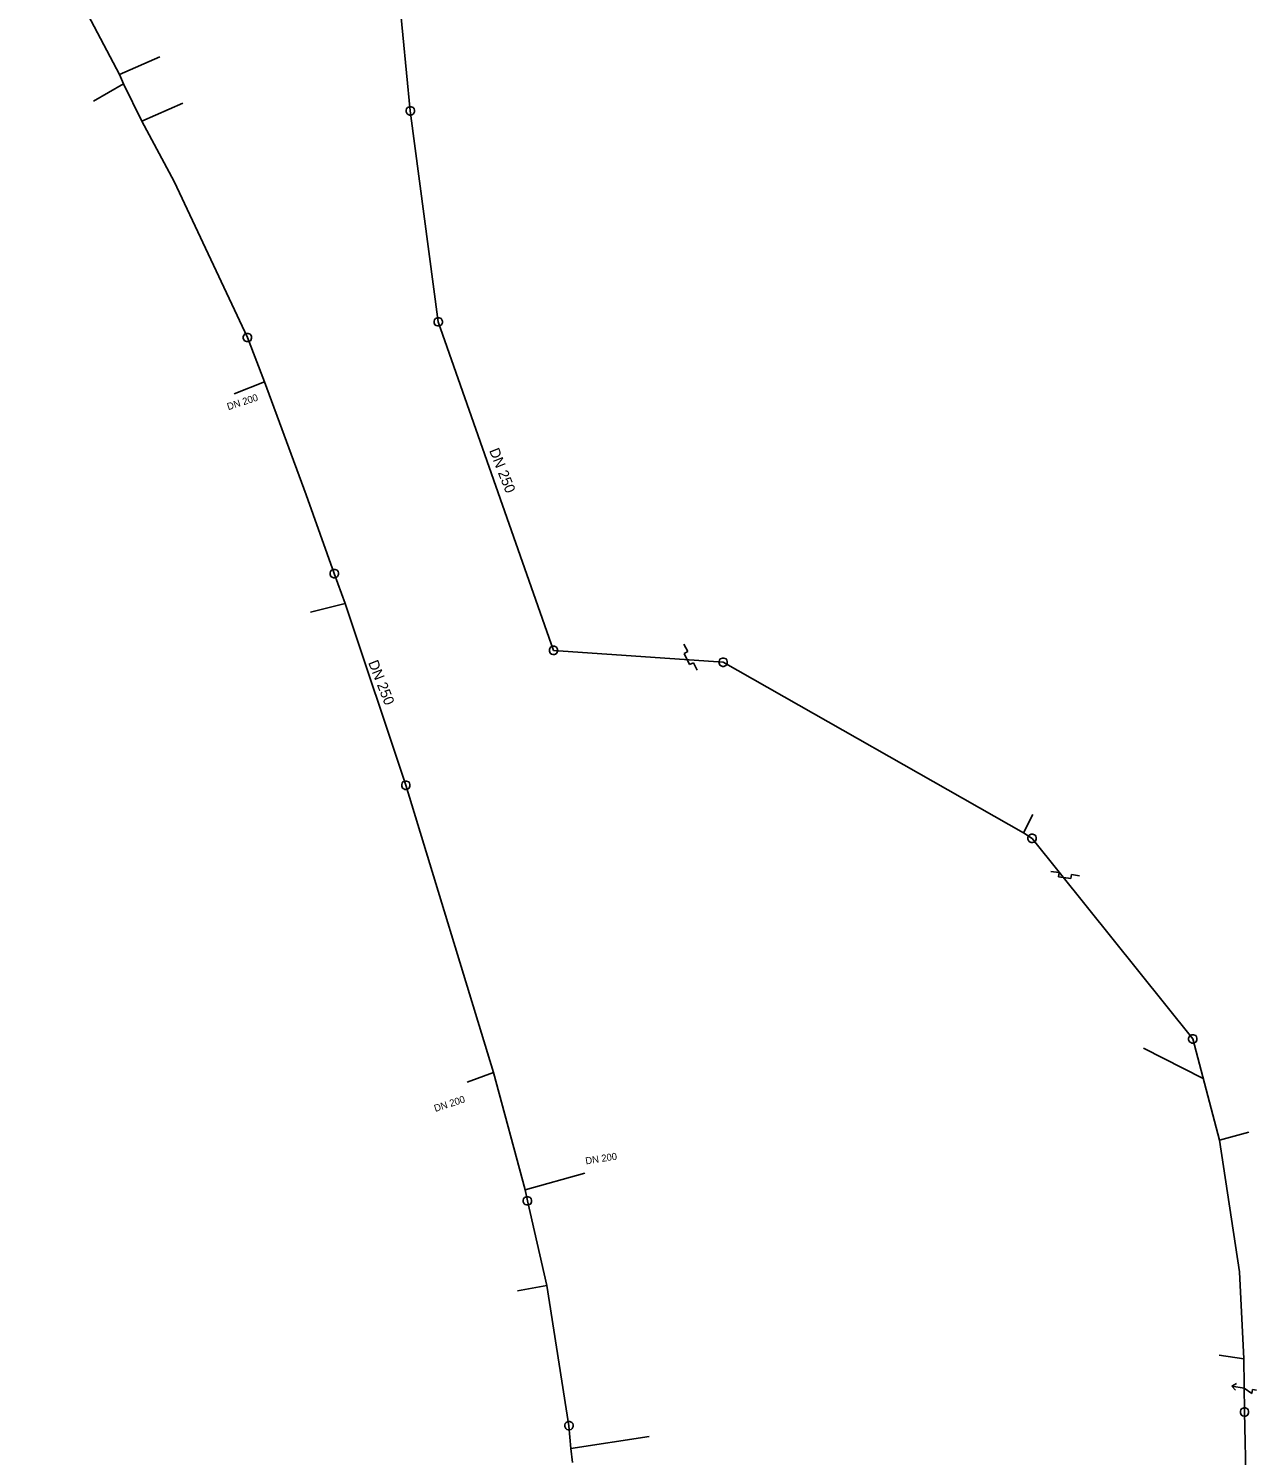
# Model space of a CAD drawing. Extents: x -717256 to -716843, y -1145423 to -1142840.
# Drawn here: x -717040.3 to -716891.8, y -1144735 to -1144562.5 of the extents above; entities that cross this region are included whole.
import ezdxf

# ---------------------------------------------------------------- set-up
doc = ezdxf.new("R2010")
doc.units = 0
for name, color, linetype in [('Vrstva 30', 7, 'Continuous'), ('Vrstva 31', 7, 'Continuous'), ('Vrstva 9', 7, 'Continuous')]:
    doc.layers.add(name, color=color, linetype=linetype)

msp = doc.modelspace()

# ---------------------------------------------------------------- linework, layer by layer
at = {"layer": 'Vrstva 30'}
for p, q in [((-716998.155, -1144530.526), (-716994.12, -1144572.47)), ((-717029.258, -1144568.056), (-717040.274, -1144547.245)), ((-717028.79, -1144569.2), (-717029.258, -1144568.056)), ((-717026.579, -1144573.721), (-717028.79, -1144569.2)), ((-716994.62, -1144572.37), (-716994.57, -1144572.22)), ((-716994.62, -1144572.57), (-716994.62, -1144572.37)), ((-716994.52, -1144572.82), (-716994.62, -1144572.57)), ((-716994.57, -1144572.22), (-716994.47, -1144572.07)), ((-716994.37, -1144572.92), (-716994.52, -1144572.82)), ((-716994.47, -1144572.07), (-716994.22, -1144571.97)), ((-716994.22, -1144572.97), (-716994.37, -1144572.92)), ((-716994.22, -1144571.97), (-716994.02, -1144571.97)), ((-716994.02, -1144572.97), (-716994.22, -1144572.97)), ((-716990.742, -1144597.967), (-716994.12, -1144572.47)), ((-716994.02, -1144571.97), (-716993.77, -1144572.07)), ((-716993.87, -1144572.92), (-716994.02, -1144572.97)), ((-716993.72, -1144572.82), (-716993.87, -1144572.92)), ((-716993.77, -1144572.07), (-716993.67, -1144572.22)), ((-716993.62, -1144572.57), (-716993.72, -1144572.82)), ((-716993.67, -1144572.22), (-716993.62, -1144572.37)), ((-716993.62, -1144572.37), (-716993.62, -1144572.57)), ((-717022.661, -1144581.009), (-717026.579, -1144573.721)), ((-717013.813, -1144599.855), (-717022.661, -1144581.009)), ((-716991.092, -1144597.567), (-716990.842, -1144597.467)), ((-716990.842, -1144597.467), (-716990.642, -1144597.467)), ((-716990.642, -1144597.467), (-716990.392, -1144597.567)), ((-716991.242, -1144597.867), (-716991.192, -1144597.717)), ((-716991.242, -1144598.067), (-716991.242, -1144597.867)), ((-716991.142, -1144598.317), (-716991.242, -1144598.067)), ((-716991.192, -1144597.717), (-716991.092, -1144597.567)), ((-716990.992, -1144598.417), (-716991.142, -1144598.317)), ((-716990.842, -1144598.467), (-716990.992, -1144598.417)), ((-716990.642, -1144598.467), (-716990.842, -1144598.467)), ((-716976.809, -1144637.685), (-716990.742, -1144597.967)), ((-716990.492, -1144598.417), (-716990.642, -1144598.467)), ((-716990.342, -1144598.317), (-716990.492, -1144598.417)), ((-716990.392, -1144597.567), (-716990.292, -1144597.717)), ((-716990.242, -1144598.067), (-716990.342, -1144598.317)), ((-716990.292, -1144597.717), (-716990.242, -1144597.867)), ((-716990.242, -1144597.867), (-716990.242, -1144598.067)), ((-717014.313, -1144599.755), (-717014.263, -1144599.605)), ((-717014.313, -1144599.955), (-717014.313, -1144599.755)), ((-717014.213, -1144600.205), (-717014.313, -1144599.955)), ((-717014.263, -1144599.605), (-717014.163, -1144599.455)), ((-717014.063, -1144600.305), (-717014.213, -1144600.205)), ((-717014.163, -1144599.455), (-717013.913, -1144599.355)), ((-717013.913, -1144600.355), (-717014.063, -1144600.305)), ((-717013.913, -1144599.355), (-717013.713, -1144599.355)), ((-717013.713, -1144600.355), (-717013.913, -1144600.355)), ((-717011.758, -1144605.221), (-717013.813, -1144599.855)), ((-717013.713, -1144599.355), (-717013.463, -1144599.455)), ((-717013.563, -1144600.305), (-717013.713, -1144600.355)), ((-717013.413, -1144600.205), (-717013.563, -1144600.305)), ((-717013.463, -1144599.455), (-717013.363, -1144599.605)), ((-717013.313, -1144599.955), (-717013.413, -1144600.205)), ((-717013.363, -1144599.605), (-717013.313, -1144599.755)), ((-717013.313, -1144599.755), (-717013.313, -1144599.955)), ((-717006.718, -1144618.872), (-717011.758, -1144605.221)), ((-717003.312, -1144628.399), (-717006.718, -1144618.872)), ((-717003.812, -1144628.299), (-717003.762, -1144628.149)), ((-717003.812, -1144628.499), (-717003.812, -1144628.299)), ((-717003.712, -1144628.749), (-717003.812, -1144628.499)), ((-717003.762, -1144628.149), (-717003.662, -1144627.999)), ((-717003.662, -1144627.999), (-717003.412, -1144627.899)), ((-717003.412, -1144627.899), (-717003.212, -1144627.899)), ((-717002.014, -1144631.998), (-717003.312, -1144628.399)), ((-717003.212, -1144627.899), (-717002.962, -1144627.999)), ((-717002.962, -1144627.999), (-717002.862, -1144628.149)), ((-717002.812, -1144628.499), (-717002.912, -1144628.749)), ((-717002.862, -1144628.149), (-717002.812, -1144628.299)), ((-717002.812, -1144628.299), (-717002.812, -1144628.499)), ((-717003.562, -1144628.849), (-717003.712, -1144628.749)), ((-717003.412, -1144628.899), (-717003.562, -1144628.849)), ((-717003.212, -1144628.899), (-717003.412, -1144628.899)), ((-717003.062, -1144628.849), (-717003.212, -1144628.899)), ((-717002.912, -1144628.749), (-717003.062, -1144628.849)), ((-716994.665, -1144653.982), (-717002.014, -1144631.998)), ((-716977.309, -1144637.585), (-716977.259, -1144637.435)), ((-716977.309, -1144637.785), (-716977.309, -1144637.585)), ((-716977.209, -1144638.035), (-716977.309, -1144637.785)), ((-716977.259, -1144637.435), (-716977.159, -1144637.285)), ((-716977.059, -1144638.135), (-716977.209, -1144638.035)), ((-716977.159, -1144637.285), (-716976.909, -1144637.185)), ((-716976.909, -1144638.185), (-716977.059, -1144638.135)), ((-716976.909, -1144637.185), (-716976.709, -1144637.185)), ((-716976.709, -1144638.185), (-716976.909, -1144638.185)), ((-716976.809, -1144637.685), (-716956.299, -1144639.117)), ((-716976.709, -1144637.185), (-716976.459, -1144637.285)), ((-716976.559, -1144638.135), (-716976.709, -1144638.185)), ((-716976.409, -1144638.035), (-716976.559, -1144638.135)), ((-716976.459, -1144637.285), (-716976.359, -1144637.435)), ((-716976.309, -1144637.785), (-716976.409, -1144638.035)), ((-716976.359, -1144637.435), (-716976.309, -1144637.585)), ((-716976.309, -1144637.585), (-716976.309, -1144637.785)), ((-716956.799, -1144639.017), (-716956.749, -1144638.867)), ((-716956.749, -1144638.867), (-716956.649, -1144638.717)), ((-716956.649, -1144638.717), (-716956.399, -1144638.617)), ((-716956.399, -1144638.617), (-716956.199, -1144638.617)), ((-716956.199, -1144638.617), (-716955.949, -1144638.717)), ((-716955.949, -1144638.717), (-716955.849, -1144638.867)), ((-716955.849, -1144638.867), (-716955.799, -1144639.017)), ((-716956.799, -1144639.217), (-716956.799, -1144639.017)), ((-716956.699, -1144639.467), (-716956.799, -1144639.217)), ((-716956.549, -1144639.567), (-716956.699, -1144639.467)), ((-716956.399, -1144639.617), (-716956.549, -1144639.567)), ((-716956.199, -1144639.617), (-716956.399, -1144639.617)), ((-716920.002, -1144659.717), (-716956.299, -1144639.117)), ((-716956.049, -1144639.567), (-716956.199, -1144639.617)), ((-716955.899, -1144639.467), (-716956.049, -1144639.567)), ((-716955.799, -1144639.217), (-716955.899, -1144639.467)), ((-716955.799, -1144639.017), (-716955.799, -1144639.217)), ((-716995.165, -1144653.882), (-716995.115, -1144653.732)), ((-716995.165, -1144654.082), (-716995.165, -1144653.882)), ((-716995.065, -1144654.332), (-716995.165, -1144654.082)), ((-716995.115, -1144653.732), (-716995.015, -1144653.582)), ((-716994.915, -1144654.432), (-716995.065, -1144654.332)), ((-716995.015, -1144653.582), (-716994.765, -1144653.482)), ((-716994.765, -1144653.482), (-716994.565, -1144653.482)), ((-716984.065, -1144688.705), (-716994.665, -1144653.982)), ((-716994.565, -1144653.482), (-716994.315, -1144653.582)), ((-716994.265, -1144654.332), (-716994.415, -1144654.432)), ((-716994.315, -1144653.582), (-716994.215, -1144653.732)), ((-716994.165, -1144654.082), (-716994.265, -1144654.332)), ((-716994.215, -1144653.732), (-716994.165, -1144653.882)), ((-716994.165, -1144653.882), (-716994.165, -1144654.082)), ((-716994.765, -1144654.482), (-716994.915, -1144654.432)), ((-716994.565, -1144654.482), (-716994.765, -1144654.482)), ((-716994.415, -1144654.432), (-716994.565, -1144654.482)), ((-716918.947, -1144660.401), (-716920.002, -1144659.717)), ((-716919.447, -1144660.301), (-716919.397, -1144660.151)), ((-716919.447, -1144660.501), (-716919.447, -1144660.301)), ((-716919.347, -1144660.751), (-716919.447, -1144660.501)), ((-716919.397, -1144660.151), (-716919.297, -1144660.001)), ((-716919.197, -1144660.851), (-716919.347, -1144660.751)), ((-716919.297, -1144660.001), (-716919.047, -1144659.901)), ((-716919.047, -1144660.901), (-716919.197, -1144660.851)), ((-716919.047, -1144659.901), (-716918.847, -1144659.901)), ((-716918.847, -1144660.901), (-716919.047, -1144660.901)), ((-716918.947, -1144660.401), (-716899.524, -1144684.642)), ((-716918.847, -1144659.901), (-716918.597, -1144660.001)), ((-716918.697, -1144660.851), (-716918.847, -1144660.901)), ((-716918.547, -1144660.751), (-716918.697, -1144660.851)), ((-716918.597, -1144660.001), (-716918.497, -1144660.151)), ((-716918.447, -1144660.501), (-716918.547, -1144660.751)), ((-716918.497, -1144660.151), (-716918.447, -1144660.301)), ((-716918.447, -1144660.301), (-716918.447, -1144660.501)), ((-716900.024, -1144684.542), (-716899.974, -1144684.392)), ((-716900.024, -1144684.742), (-716900.024, -1144684.542)), ((-716899.924, -1144684.992), (-716900.024, -1144684.742)), ((-716899.974, -1144684.392), (-716899.874, -1144684.242)), ((-716899.774, -1144685.092), (-716899.924, -1144684.992)), ((-716899.874, -1144684.242), (-716899.624, -1144684.142)), ((-716899.624, -1144685.142), (-716899.774, -1144685.092)), ((-716899.624, -1144684.142), (-716899.424, -1144684.142)), ((-716899.424, -1144685.142), (-716899.624, -1144685.142)), ((-716899.524, -1144684.642), (-716896.302, -1144696.881)), ((-716899.424, -1144684.142), (-716899.174, -1144684.242)), ((-716899.274, -1144685.092), (-716899.424, -1144685.142)), ((-716899.124, -1144684.992), (-716899.274, -1144685.092)), ((-716899.174, -1144684.242), (-716899.074, -1144684.392)), ((-716899.024, -1144684.742), (-716899.124, -1144684.992)), ((-716899.074, -1144684.392), (-716899.024, -1144684.542)), ((-716899.024, -1144684.542), (-716899.024, -1144684.742)), ((-716980.224, -1144702.883), (-716984.065, -1144688.705)), ((-716896.302, -1144696.881), (-716893.89, -1144712.784)), ((-716980.468, -1144704.121), (-716980.418, -1144703.971)), ((-716980.468, -1144704.321), (-716980.468, -1144704.121)), ((-716980.368, -1144704.571), (-716980.468, -1144704.321)), ((-716980.418, -1144703.971), (-716980.318, -1144703.821)), ((-716980.318, -1144703.821), (-716980.068, -1144703.721)), ((-716979.968, -1144704.221), (-716980.224, -1144702.883)), ((-716980.068, -1144703.721), (-716979.868, -1144703.721)), ((-716977.636, -1144714.449), (-716979.968, -1144704.221)), ((-716979.868, -1144703.721), (-716979.618, -1144703.821)), ((-716979.618, -1144703.821), (-716979.518, -1144703.971)), ((-716979.468, -1144704.321), (-716979.568, -1144704.571)), ((-716979.518, -1144703.971), (-716979.468, -1144704.121)), ((-716979.468, -1144704.121), (-716979.468, -1144704.321)), ((-716980.218, -1144704.671), (-716980.368, -1144704.571)), ((-716980.068, -1144704.721), (-716980.218, -1144704.671)), ((-716979.868, -1144704.721), (-716980.068, -1144704.721)), ((-716979.718, -1144704.671), (-716979.868, -1144704.721)), ((-716979.568, -1144704.571), (-716979.718, -1144704.671)), ((-716893.89, -1144712.784), (-716893.338, -1144723.308)), ((-716974.937, -1144731.397), (-716977.636, -1144714.449)), ((-716893.338, -1144723.308), (-716893.27, -1144729.746)), ((-716893.77, -1144729.646), (-716893.72, -1144729.496)), ((-716893.77, -1144729.846), (-716893.77, -1144729.646)), ((-716893.67, -1144730.096), (-716893.77, -1144729.846)), ((-716893.72, -1144729.496), (-716893.62, -1144729.346)), ((-716893.52, -1144730.196), (-716893.67, -1144730.096)), ((-716893.62, -1144729.346), (-716893.37, -1144729.246)), ((-716893.37, -1144730.246), (-716893.52, -1144730.196)), ((-716893.37, -1144729.246), (-716893.17, -1144729.246)), ((-716893.17, -1144730.246), (-716893.37, -1144730.246)), ((-716893.27, -1144729.746), (-716892.366, -1144767.564)), ((-716893.17, -1144729.246), (-716892.92, -1144729.346)), ((-716893.02, -1144730.196), (-716893.17, -1144730.246)), ((-716892.87, -1144730.096), (-716893.02, -1144730.196)), ((-716892.92, -1144729.346), (-716892.82, -1144729.496)), ((-716892.77, -1144729.846), (-716892.87, -1144730.096)), ((-716892.82, -1144729.496), (-716892.77, -1144729.646)), ((-716892.77, -1144729.646), (-716892.77, -1144729.846)), ((-716975.437, -1144731.297), (-716975.387, -1144731.147)), ((-716975.437, -1144731.497), (-716975.437, -1144731.297)), ((-716975.337, -1144731.747), (-716975.437, -1144731.497)), ((-716975.387, -1144731.147), (-716975.287, -1144730.997)), ((-716975.187, -1144731.847), (-716975.337, -1144731.747)), ((-716975.287, -1144730.997), (-716975.037, -1144730.897)), ((-716975.037, -1144731.897), (-716975.187, -1144731.847)), ((-716975.037, -1144730.897), (-716974.837, -1144730.897)), ((-716974.837, -1144731.897), (-716975.037, -1144731.897)), ((-716974.721, -1144734.14), (-716974.937, -1144731.397)), ((-716974.837, -1144730.897), (-716974.587, -1144730.997)), ((-716974.687, -1144731.847), (-716974.837, -1144731.897)), ((-716974.537, -1144731.747), (-716974.687, -1144731.847)), ((-716974.587, -1144730.997), (-716974.487, -1144731.147)), ((-716974.437, -1144731.497), (-716974.537, -1144731.747)), ((-716974.487, -1144731.147), (-716974.437, -1144731.297)), ((-716974.437, -1144731.297), (-716974.437, -1144731.497)), ((-716974.505, -1144735.855), (-716974.721, -1144734.14))]:
    msp.add_line(p, q, dxfattribs=at)
at = {"layer": 'Vrstva 31'}
for p, q in [((-717029.258, -1144568.056), (-717024.409, -1144565.948)), ((-717028.79, -1144569.2), (-717032.43, -1144571.301)), ((-717026.579, -1144573.721), (-717021.612, -1144571.539)), ((-717011.758, -1144605.221), (-717015.411, -1144606.674)), ((-717002.014, -1144631.998), (-717006.205, -1144633.058)), ((-716920.002, -1144659.717), (-716918.855, -1144657.514)), ((-716905.473, -1144685.75), (-716898.259, -1144689.445)), ((-716984.065, -1144688.705), (-716987.261, -1144689.889)), ((-716896.302, -1144696.881), (-716892.751, -1144695.914)), ((-716980.224, -1144702.883), (-716973.03, -1144700.854)), ((-716977.636, -1144714.449), (-716981.16, -1144715.116)), ((-716896.33, -1144722.857), (-716893.338, -1144723.308)), ((-716974.721, -1144734.14), (-716965.228, -1144732.72))]:
    msp.add_line(p, q, dxfattribs=at)
at = {"layer": 'Vrstva 9'}
for p, q in [((-716961.04, -1144636.937), (-716960.586, -1144637.828)), ((-716960.586, -1144637.828), (-716961.032, -1144638.055)), ((-716961.032, -1144638.055), (-716960.351, -1144639.392)), ((-716960.351, -1144639.392), (-716959.905, -1144639.165)), ((-716959.905, -1144639.165), (-716959.451, -1144640.056)), ((-716916.667, -1144664.389), (-716915.679, -1144664.545)), ((-716915.679, -1144664.545), (-716915.757, -1144665.039)), ((-716915.757, -1144665.039), (-716914.276, -1144665.274)), ((-716914.276, -1144665.274), (-716914.198, -1144664.78)), ((-716914.198, -1144664.78), (-716913.21, -1144664.936)), ((-716894.79, -1144726.622), (-716894.234, -1144726.305)), ((-716893.309, -1144726.857), (-716894.79, -1144726.622)), ((-716894.359, -1144727.095), (-716894.79, -1144726.622)), ((-716892.399, -1144727.507), (-716893.309, -1144726.857)), ((-716892.321, -1144727.013), (-716892.399, -1144727.507)), ((-716891.827, -1144727.091), (-716892.321, -1144727.013))]:
    msp.add_line(p, q, dxfattribs=at)

# ---------------------------------------------------------------- texts
at = {"layer": 'Vrstva 30'}
for p in [(-716984.609, -1144613.516), (-716999.235, -1144639.152)]:
    msp.add_text('DN 250', height=1.25, rotation=291.6, dxfattribs=at).set_placement(p)
at = {"layer": 'Vrstva 31'}
for rotation, p in [(18, (-717016.12, -1144608.65)), (18, (-716991.09, -1144693.476)), (9, (-716972.886, -1144699.821))]:
    msp.add_text('DN 200', height=0.85, rotation=rotation, dxfattribs=at).set_placement(p)

doc.saveas('drawing.dxf')
